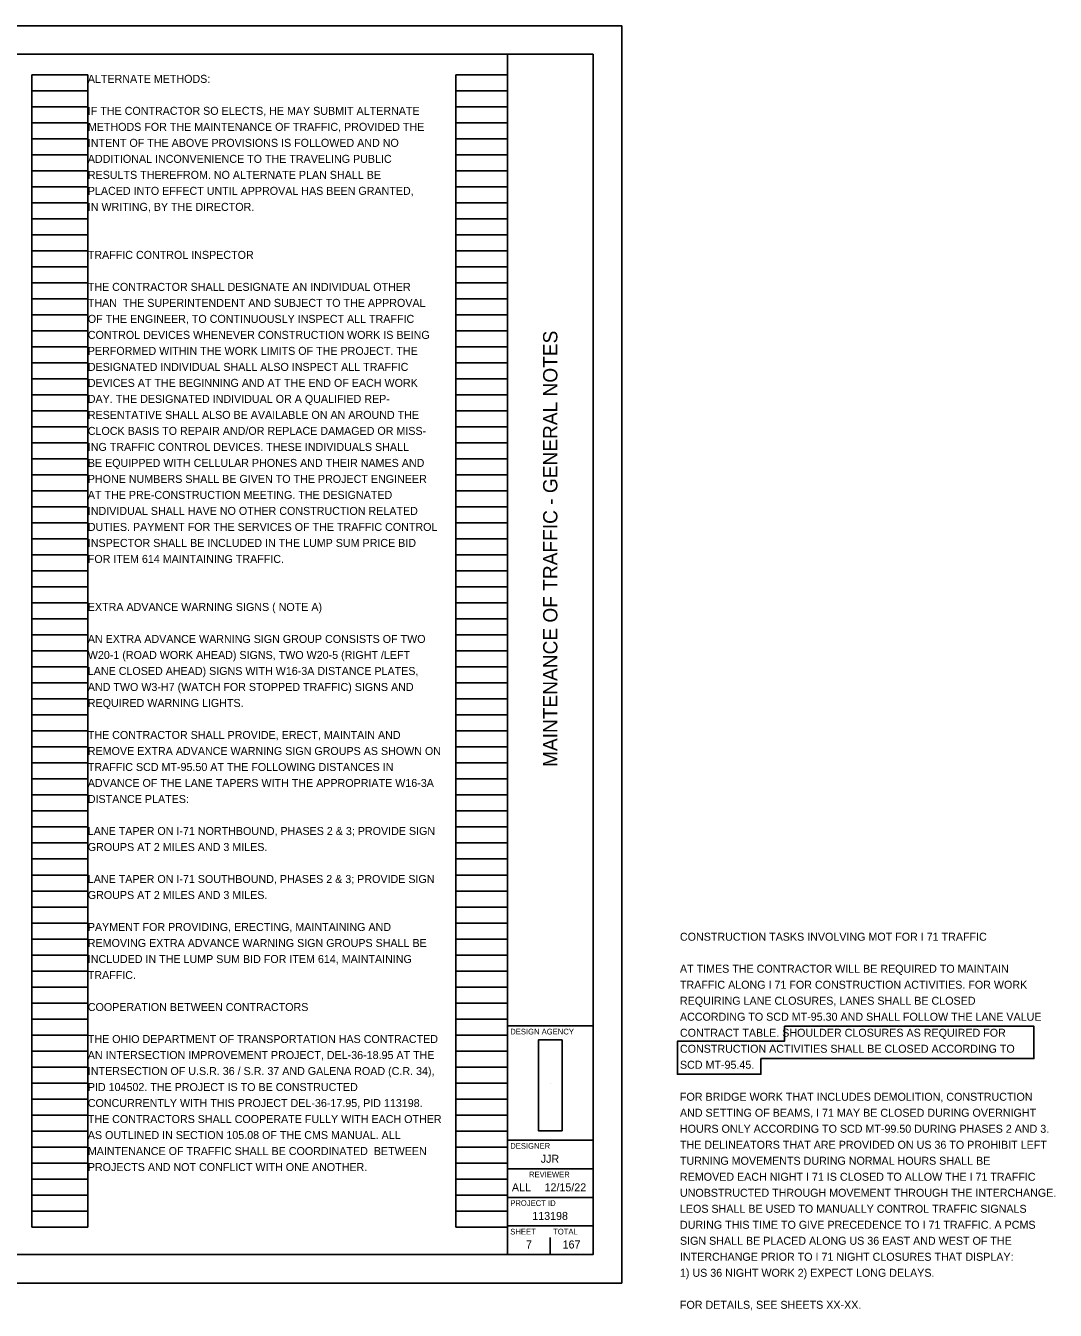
# Model space of a CAD drawing. Extents: x 0 to 41.6, y -0.5 to 22.
# Drawn here: x 23.57 to 41.59, y -0.48 to 22 of the extents above; entities that cross this region are included whole.
import ezdxf

# ---------------------------------------------------------------- set-up
doc = ezdxf.new("R2010")
doc.units = 0
for name, color, linetype in [('Default', 7, 'Continuous'), ('SH_Border', 7, 'Continuous'), ('SH_Cut_Line', 7, 'Continuous'), ('SH_Data', 7, 'Continuous'), ('SH_Text', 7, 'Continuous')]:
    doc.layers.add(name, color=color, linetype=linetype)

msp = doc.modelspace()

# ---------------------------------------------------------------- linework, layer by layer
at = {"layer": 'SH_Border'}
for p, q in [((32, 0.5), (32, 21.5)), ((32, 4.5), (33.5, 4.5)), ((32, 2.5), (33.5, 2.5)), ((32, 2), (33.5, 2)), ((32, 1.5), (33.5, 1.5)), ((32, 1), (33.5, 1))]:
    msp.add_line(p, q, dxfattribs=at)
msp.add_lwpolyline([(1.5, 21.5), (33.5, 21.5), (33.5, 0.5), (1.5, 0.5)], close=True, dxfattribs=at)
at = {"layer": 'SH_Cut_Line'}
msp.add_lwpolyline([(0, 0), (34, 0), (34, 22), (0, 22)], close=True, dxfattribs=at)
at = {"layer": 'SH_Data'}
for p, q in [((23.68, 0.98), (23.68, 21.14)), ((23.68, 21.14), (24.66, 21.14)), ((24.66, 0.98), (24.66, 21.14)), ((31.1, 0.98), (31.1, 21.14)), ((31.1, 21.14), (32, 21.14)), ((32, 0.98), (32, 21.14)), ((23.68, 20.86), (24.66, 20.86)), ((31.1, 20.86), (32, 20.86)), ((23.68, 20.58), (24.66, 20.58)), ((31.1, 20.58), (32, 20.58)), ((23.68, 20.3), (24.66, 20.3)), ((31.1, 20.3), (32, 20.3)), ((23.68, 20.02), (24.66, 20.02)), ((31.1, 20.02), (32, 20.02)), ((23.68, 19.74), (24.66, 19.74)), ((31.1, 19.74), (32, 19.74)), ((23.68, 19.46), (24.66, 19.46)), ((31.1, 19.46), (32, 19.46)), ((23.68, 19.18), (24.66, 19.18)), ((31.1, 19.18), (32, 19.18)), ((23.68, 18.9), (24.66, 18.9)), ((31.1, 18.9), (32, 18.9)), ((23.68, 18.62), (24.66, 18.62)), ((31.1, 18.62), (32, 18.62)), ((23.68, 18.34), (24.66, 18.34)), ((31.1, 18.34), (32, 18.34)), ((23.68, 18.06), (24.66, 18.06)), ((31.1, 18.06), (32, 18.06)), ((23.68, 17.78), (24.66, 17.78)), ((31.1, 17.78), (32, 17.78)), ((23.68, 17.5), (24.66, 17.5)), ((31.1, 17.5), (32, 17.5)), ((23.68, 17.22), (24.66, 17.22)), ((31.1, 17.22), (32, 17.22)), ((23.68, 16.94), (24.66, 16.94)), ((31.1, 16.94), (32, 16.94)), ((23.68, 16.66), (24.66, 16.66)), ((31.1, 16.66), (32, 16.66)), ((23.68, 16.38), (24.66, 16.38)), ((31.1, 16.38), (32, 16.38)), ((23.68, 16.1), (24.66, 16.1)), ((31.1, 16.1), (32, 16.1)), ((23.68, 15.82), (24.66, 15.82)), ((31.1, 15.82), (32, 15.82)), ((23.68, 15.54), (24.66, 15.54)), ((31.1, 15.54), (32, 15.54)), ((23.68, 15.26), (24.66, 15.26)), ((31.1, 15.26), (32, 15.26)), ((23.68, 14.98), (24.66, 14.98)), ((31.1, 14.98), (32, 14.98)), ((23.68, 14.7), (24.66, 14.7)), ((31.1, 14.7), (32, 14.7)), ((23.68, 14.42), (24.66, 14.42)), ((31.1, 14.42), (32, 14.42)), ((23.68, 14.14), (24.66, 14.14)), ((31.1, 14.14), (32, 14.14)), ((23.68, 13.86), (24.66, 13.86)), ((31.1, 13.86), (32, 13.86)), ((23.68, 13.58), (24.66, 13.58)), ((31.1, 13.58), (32, 13.58)), ((23.68, 13.3), (24.66, 13.3)), ((31.1, 13.3), (32, 13.3)), ((23.68, 13.02), (24.66, 13.02)), ((31.1, 13.02), (32, 13.02)), ((23.68, 12.74), (24.66, 12.74)), ((31.1, 12.74), (32, 12.74)), ((23.68, 12.46), (24.66, 12.46)), ((31.1, 12.46), (32, 12.46)), ((23.68, 12.18), (24.66, 12.18)), ((31.1, 12.18), (32, 12.18)), ((23.68, 11.9), (24.66, 11.9)), ((31.1, 11.9), (32, 11.9)), ((23.68, 11.62), (24.66, 11.62)), ((31.1, 11.62), (32, 11.62)), ((23.68, 11.34), (24.66, 11.34)), ((31.1, 11.34), (32, 11.34)), ((23.68, 11.06), (24.66, 11.06)), ((31.1, 11.06), (32, 11.06)), ((23.68, 10.78), (24.66, 10.78)), ((31.1, 10.78), (32, 10.78)), ((23.68, 10.5), (24.66, 10.5)), ((31.1, 10.5), (32, 10.5)), ((23.68, 10.22), (24.66, 10.22)), ((31.1, 10.22), (32, 10.22)), ((23.68, 9.94), (24.66, 9.94)), ((31.1, 9.94), (32, 9.94)), ((23.68, 9.66), (24.66, 9.66)), ((31.1, 9.66), (32, 9.66)), ((23.68, 9.38), (24.66, 9.38)), ((31.1, 9.38), (32, 9.38)), ((23.68, 9.1), (24.66, 9.1)), ((31.1, 9.1), (32, 9.1)), ((23.68, 8.82), (24.66, 8.82)), ((31.1, 8.82), (32, 8.82)), ((23.68, 8.54), (24.66, 8.54)), ((31.1, 8.54), (32, 8.54)), ((23.68, 8.26), (24.66, 8.26)), ((31.1, 8.26), (32, 8.26)), ((23.68, 7.98), (24.66, 7.98)), ((31.1, 7.98), (32, 7.98)), ((23.68, 7.7), (24.66, 7.7)), ((31.1, 7.7), (32, 7.7)), ((23.68, 7.42), (24.66, 7.42)), ((31.1, 7.42), (32, 7.42)), ((23.68, 7.14), (24.66, 7.14)), ((31.1, 7.14), (32, 7.14)), ((23.68, 6.86), (24.66, 6.86)), ((31.1, 6.86), (32, 6.86)), ((23.68, 6.58), (24.66, 6.58)), ((31.1, 6.58), (32, 6.58)), ((23.68, 6.3), (24.66, 6.3)), ((31.1, 6.3), (32, 6.3)), ((23.68, 6.02), (24.66, 6.02)), ((31.1, 6.02), (32, 6.02)), ((23.68, 5.74), (24.66, 5.74)), ((31.1, 5.74), (32, 5.74)), ((23.68, 5.46), (24.66, 5.46)), ((31.1, 5.46), (32, 5.46)), ((23.68, 5.18), (24.66, 5.18)), ((31.1, 5.18), (32, 5.18)), ((23.68, 4.9), (24.66, 4.9)), ((31.1, 4.9), (32, 4.9)), ((23.68, 4.62), (24.66, 4.62)), ((31.1, 4.62), (32, 4.62)), ((23.68, 4.34), (24.66, 4.34)), ((31.1, 4.34), (32, 4.34)), ((23.68, 4.06), (24.66, 4.06)), ((31.1, 4.06), (32, 4.06)), ((23.68, 3.78), (24.66, 3.78)), ((31.1, 3.78), (32, 3.78)), ((23.68, 3.5), (24.66, 3.5)), ((31.1, 3.5), (32, 3.5)), ((32.75, 3.5), (32.75, 3.5)), ((23.68, 3.22), (24.66, 3.22)), ((31.1, 3.22), (32, 3.22)), ((23.68, 2.94), (24.66, 2.94)), ((31.1, 2.94), (32, 2.94)), ((23.68, 2.66), (24.66, 2.66)), ((31.1, 2.66), (32, 2.66)), ((23.68, 2.38), (24.66, 2.38)), ((31.1, 2.38), (32, 2.38)), ((23.68, 2.1), (24.66, 2.1)), ((31.1, 2.1), (32, 2.1)), ((23.68, 1.82), (24.66, 1.82)), ((31.1, 1.82), (32, 1.82)), ((23.68, 1.54), (24.66, 1.54)), ((31.1, 1.54), (32, 1.54)), ((23.68, 1.26), (24.66, 1.26)), ((31.1, 1.26), (32, 1.26)), ((23.68, 0.98), (24.66, 0.98)), ((31.1, 0.98), (32, 0.98)), ((32.375, 0.675), (32.375, 0.675)), ((32.75, 0.5), (32.75, 0.8))]:
    msp.add_line(p, q, dxfattribs=at)
at = {"layer": 'SH_Text'}
msp.add_lwpolyline([(36.846, 4.495), (36.846, 4.23), (34.975, 4.23), (34.975, 3.655), (36.435, 3.655), (36.435, 3.929), (41.21, 3.929), (41.21, 4.495), (36.846, 4.495)], dxfattribs=at)
msp.add_lwpolyline([(32.956, 2.664), (32.956, 4.254), (32.544, 4.254), (32.544, 2.664)], close=True, dxfattribs=at)

# ---------------------------------------------------------------- texts
at = {"layer": 'Default'}
for s, p in [('ALTERNATE METHODS:', (24.66, 21)), ('IF THE CONTRACTOR SO ELECTS, HE MAY SUBMIT ALTERNATE', (24.66, 20.44)), ('METHODS FOR THE MAINTENANCE OF TRAFFIC, PROVIDED THE', (24.66, 20.16)), ('INTENT OF THE ABOVE PROVISIONS IS FOLLOWED AND NO', (24.66, 19.88)), ('ADDITIONAL INCONVENIENCE TO THE TRAVELING PUBLIC', (24.66, 19.6)), ('RESULTS THEREFROM. NO ALTERNATE PLAN SHALL BE', (24.66, 19.32)), ('PLACED INTO EFFECT UNTIL APPROVAL HAS BEEN GRANTED,', (24.66, 19.04)), ('IN WRITING, BY THE DIRECTOR.', (24.66, 18.76)), ('CONSTRUCTION TASKS INVOLVING MOT FOR I 71 TRAFFIC', (35.019, 5.99))]:
    msp.add_text(s, height=0.14, dxfattribs=at).set_placement(p)
at = {"layer": 'SH_Data'}
msp.add_text('MAINTENANCE OF TRAFFIC - GENERAL NOTES', height=0.25, rotation=90, dxfattribs=at).set_placement((32.875, 9.03))
for s, height, p in [('DESIGN AGENCY', 0.1, (32.05, 4.35)), ('DESIGNER', 0.1, (32.05, 2.35)), ('JJR', 0.14, (32.583, 2.105)), ('REVIEWER', 0.1, (32.378, 1.85)), ('ALL', 0.14, (32.079, 1.605)), ('12/15/22', 0.14, (32.65, 1.605)), ('PROJECT ID', 0.1, (32.05, 1.35)), ('113198', 0.14, (32.435, 1.105)), ('SHEET', 0.1, (32.05, 0.85)), ('TOTAL', 0.1, (32.8, 0.85)), ('7', 0.14, (32.325, 0.605)), ('167', 0.14, (32.966, 0.605))]:
    msp.add_text(s, height=height, dxfattribs=at).set_placement(p)
at = {"layer": 'SH_Text'}
for s, p in [('TRAFFIC CONTROL INSPECTOR', (24.66, 17.92)), ('THE CONTRACTOR SHALL DESIGNATE AN INDIVIDUAL OTHER', (24.66, 17.36)), ('THAN  THE SUPERINTENDENT AND SUBJECT TO THE APPROVAL', (24.66, 17.08)), ('OF THE ENGINEER, TO CONTINUOUSLY INSPECT ALL TRAFFIC', (24.66, 16.8)), ('CONTROL DEVICES WHENEVER CONSTRUCTION WORK IS BEING', (24.66, 16.52)), ('PERFORMED WITHIN THE WORK LIMITS OF THE PROJECT. THE', (24.66, 16.24)), ('DESIGNATED INDIVIDUAL SHALL ALSO INSPECT ALL TRAFFIC', (24.66, 15.96)), ('DEVICES AT THE BEGINNING AND AT THE END OF EACH WORK', (24.66, 15.68)), ('DAY. THE DESIGNATED INDIVIDUAL OR A QUALIFIED REP-', (24.66, 15.4)), ('RESENTATIVE SHALL ALSO BE AVAILABLE ON AN AROUND THE', (24.66, 15.12)), ('CLOCK BASIS TO REPAIR AND/OR REPLACE DAMAGED OR MISS-', (24.66, 14.84)), ('ING TRAFFIC CONTROL DEVICES. THESE INDIVIDUALS SHALL', (24.66, 14.56)), ('BE EQUIPPED WITH CELLULAR PHONES AND THEIR NAMES AND', (24.66, 14.28)), ('PHONE NUMBERS SHALL BE GIVEN TO THE PROJECT ENGINEER', (24.66, 14)), ('AT THE PRE-CONSTRUCTION MEETING. THE DESIGNATED', (24.66, 13.72)), ('INDIVIDUAL SHALL HAVE NO OTHER CONSTRUCTION RELATED', (24.66, 13.44)), ('DUTIES. PAYMENT FOR THE SERVICES OF THE TRAFFIC CONTROL', (24.66, 13.16)), ('INSPECTOR SHALL BE INCLUDED IN THE LUMP SUM PRICE BID', (24.66, 12.88)), ('FOR ITEM 614 MAINTAINING TRAFFIC.', (24.66, 12.6)), ('EXTRA ADVANCE WARNING SIGNS ( NOTE A)', (24.66, 11.76)), ('AN EXTRA ADVANCE WARNING SIGN GROUP CONSISTS OF TWO ', (24.66, 11.2)), ('W20-1 (ROAD WORK AHEAD) SIGNS, TWO W20-5 (RIGHT /LEFT ', (24.66, 10.92)), ('LANE CLOSED AHEAD) SIGNS WITH W16-3A DISTANCE PLATES, ', (24.66, 10.64)), ('AND TWO W3-H7 (WATCH FOR STOPPED TRAFFIC) SIGNS AND ', (24.66, 10.36)), ('REQUIRED WARNING LIGHTS. ', (24.66, 10.08)), ('THE CONTRACTOR SHALL PROVIDE, ERECT, MAINTAIN AND ', (24.66, 9.52)), ('REMOVE EXTRA ADVANCE WARNING SIGN GROUPS AS SHOWN ON ', (24.66, 9.24)), ('TRAFFIC SCD MT-95.50 AT THE FOLLOWING DISTANCES IN ', (24.66, 8.96)), ('ADVANCE OF THE LANE TAPERS WITH THE APPROPRIATE W16-3A ', (24.66, 8.68)), ('DISTANCE PLATES: ', (24.66, 8.4)), ('LANE TAPER ON I-71 NORTHBOUND, PHASES 2 & 3; PROVIDE SIGN ', (24.66, 7.84)), ('GROUPS AT 2 MILES AND 3 MILES.', (24.66, 7.56)), ('LANE TAPER ON I-71 SOUTHBOUND, PHASES 2 & 3; PROVIDE SIGN ', (24.66, 7)), ('GROUPS AT 2 MILES AND 3 MILES.', (24.66, 6.72)), ('PAYMENT FOR PROVIDING, ERECTING, MAINTAINING AND ', (24.66, 6.16)), ('REMOVING EXTRA ADVANCE WARNING SIGN GROUPS SHALL BE ', (24.66, 5.88)), ('INCLUDED IN THE LUMP SUM BID FOR ITEM 614, MAINTAINING ', (24.66, 5.6)), ('TRAFFIC. ', (24.66, 5.32)), ('AT TIMES THE CONTRACTOR WILL BE REQUIRED TO MAINTAIN', (35.019, 5.43)), ('TRAFFIC ALONG I 71 FOR CONSTRUCTION ACTIVITIES. FOR WORK', (35.019, 5.15)), ('REQUIRING LANE CLOSURES, LANES SHALL BE CLOSED', (35.019, 4.87)), ('COOPERATION BETWEEN CONTRACTORS', (24.66, 4.76)), ('ACCORDING TO SCD MT-95.30 AND SHALL FOLLOW THE LANE VALUE', (35.019, 4.59)), ('THE OHIO DEPARTMENT OF TRANSPORTATION HAS CONTRACTED ', (24.66, 4.2)), ('CONTRACT TABLE. SHOULDER CLOSURES AS REQUIRED FOR', (35.019, 4.31)), ('AN INTERSECTION IMPROVEMENT PROJECT, DEL-36-18.95 AT THE ', (24.66, 3.92)), ('CONSTRUCTION ACTIVITIES SHALL BE CLOSED ACCORDING TO ', (35.019, 4.03)), ('SCD MT-95.45.', (35.019, 3.75)), ('INTERSECTION OF U.S.R. 36 / S.R. 37 AND GALENA ROAD (C.R. 34), ', (24.66, 3.64)), ('PID 104502. THE PROJECT IS TO BE CONSTRUCTED ', (24.66, 3.36)), ('CONCURRENTLY WITH THIS PROJECT DEL-36-17.95, PID 113198. ', (24.66, 3.08)), ('FOR BRIDGE WORK THAT INCLUDES DEMOLITION, CONSTRUCTION ', (35.019, 3.19)), ('THE CONTRACTORS SHALL COOPERATE FULLY WITH EACH OTHER ', (24.66, 2.8)), ('AND SETTING OF BEAMS, I 71 MAY BE CLOSED DURING OVERNIGHT', (35.019, 2.91)), ('HOURS ONLY ACCORDING TO SCD MT-99.50 DURING PHASES 2 AND 3.', (35.019, 2.63)), ('AS OUTLINED IN SECTION 105.08 OF THE CMS MANUAL. ALL ', (24.66, 2.52)), ('THE DELINEATORS THAT ARE PROVIDED ON US 36 TO PROHIBIT LEFT', (35.019, 2.35)), ('MAINTENANCE OF TRAFFIC SHALL BE COORDINATED  BETWEEN ', (24.66, 2.24)), ('PROJECTS AND NOT CONFLICT WITH ONE ANOTHER.', (24.66, 1.96)), ('TURNING MOVEMENTS DURING NORMAL HOURS SHALL BE ', (35.019, 2.07)), ('REMOVED EACH NIGHT I 71 IS CLOSED TO ALLOW THE I 71 TRAFFIC', (35.019, 1.79)), ('UNOBSTRUCTED THROUGH MOVEMENT THROUGH THE INTERCHANGE.', (35.019, 1.51)), ('LEOS SHALL BE USED TO MANUALLY CONTROL TRAFFIC SIGNALS', (35.019, 1.23)), ('DURING THIS TIME TO GIVE PRECEDENCE TO I 71 TRAFFIC. A PCMS', (35.019, 0.95)), ('SIGN SHALL BE PLACED ALONG US 36 EAST AND WEST OF THE', (35.019, 0.67)), ('INTERCHANGE PRIOR TO I 71 NIGHT CLOSURES THAT DISPLAY:', (35.019, 0.39)), ('1) US 36 NIGHT WORK 2) EXPECT LONG DELAYS.  ', (35.019, 0.11)), ('FOR DETAILS, SEE SHEETS XX-XX.', (35.019, -0.45))]:
    msp.add_text(s, height=0.14, dxfattribs=at).set_placement(p)

doc.saveas('drawing.dxf')
